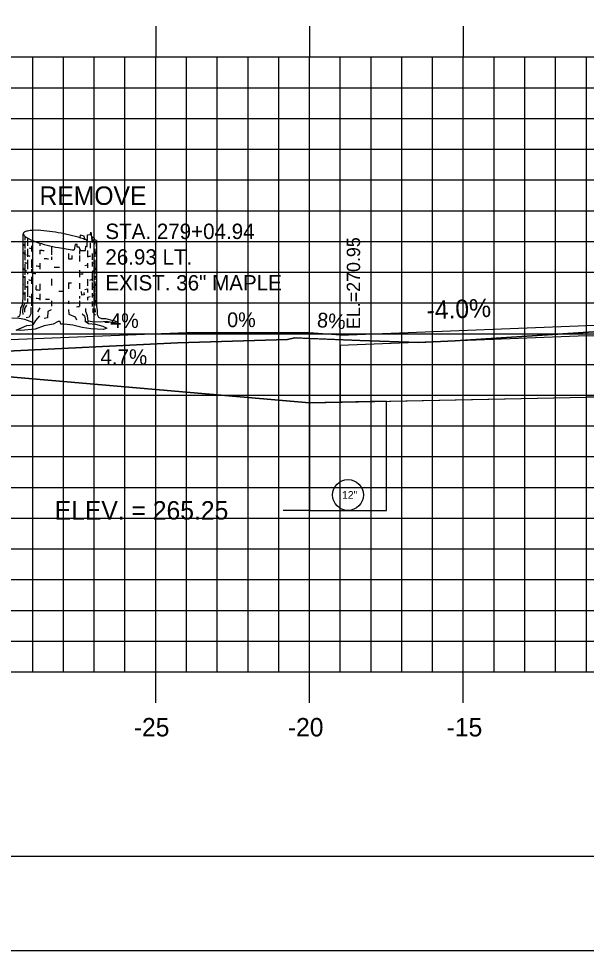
# Model space of a CAD drawing. Extents: x 854899 to 855069, y 366268 to 366378.
# Drawn here: x 854952.32 to 854970.77, y 366268.18 to 366298.48 of the extents above; entities that cross this region are included whole.
import ezdxf

# ---------------------------------------------------------------- set-up
doc = ezdxf.new("R2010")
doc.units = 0
for name, color, linetype in [('ANNOTATION', 7, 'Continuous'), ('BORDER', 7, 'Continuous'), ('D_Roadway_Drive_Gravel_LT', 7, 'Continuous'), ('D_Roadway_Drive_Gravel_RT', 7, 'Continuous'), ('D_Roadway_Drive_SubGrade', 7, 'Continuous'), ('D_Roadway_Edge_Shoulder', 7, 'Continuous'), ('D_Roadway_SubGrade', 7, 'Continuous'), ('D_Text_Monospaced', 7, 'Continuous'), ('D_Text_Standard', 7, 'Continuous'), ('H_V ANNOTATION', 7, 'Continuous'), ('JUNK COM EXC', 7, 'Continuous'), ('junk strct exc', 7, 'Continuous'), ('MAJOR', 7, 'Continuous'), ('MINOR', 7, 'Continuous'), ('PDRAIN', 7, 'Continuous'), ('PLOT BOUNDARY', 7, 'Continuous'), ('S_Roadway_Centerline', 7, 'Continuous'), ('S_Trees_Decid_Pay', 7, 'Continuous'), ('TEXT', 7, 'Continuous')]:
    doc.layers.add(name, color=color, linetype=linetype)

msp = doc.modelspace()

# ---------------------------------------------------------------- linework, layer by layer
at = {"layer": 'BORDER'}
msp.add_line((854906.774, 366271.236), (855066.774, 366271.236), dxfattribs=at)
at = {"layer": 'D_Roadway_Drive_Gravel_LT'}
for p, q in [((854961.774, 366288.264), (854957.774, 366288.264)), ((854962.774, 366288.184), (854961.774, 366288.264))]:
    msp.add_line(p, q, dxfattribs=at)
at = {"layer": 'D_Roadway_Drive_Gravel_RT'}
msp.add_line((854957.774, 366288.264), (854951.774, 366288.024), dxfattribs=at)
at = {"layer": 'D_Roadway_Drive_SubGrade'}
for p, q in [((854961.774, 366285.991), (854951.774, 366286.853)), ((854962.774, 366286.011), (854961.774, 366285.991))]:
    msp.add_line(p, q, dxfattribs=at)
at = {"layer": 'D_Roadway_Edge_Shoulder'}
msp.add_lwpolyline([(854962.774, 366288.184), (854970.774, 366288.504), (854981.774, 366288.674), (854992.774, 366288.453), (855000.774, 366288.133)], dxfattribs=at)
at = {"layer": 'D_Roadway_SubGrade'}
for points in [[(854970.774, 366288.171), (854962.774, 366287.851), (854962.774, 366286.011), (854970.774, 366286.171)], [(854970.774, 366286.171), (854970.774, 366288.171), (854981.774, 366288.34), (854992.774, 366288.12), (854992.774, 366286.12), (854981.774, 366286.34)]]:
    msp.add_lwpolyline(points, close=True, dxfattribs=at)
at = {"layer": 'D_Text_Standard'}
msp.add_lwpolyline([(854961.774, 366282.49), (854961.597, 366282.49), (854960.917, 366282.49)], dxfattribs=at)
at = {"layer": 'JUNK COM EXC'}
msp.add_lwpolyline([(855001.774, 366288.529), (854999.893, 366288.419), (854999.77, 366288.409), (854996.433, 366288.257), (854996.105, 366288.282), (854993.573, 366288.403), (854989.068, 366288.497), (854982.457, 366288.64), (854977.246, 366288.416), (854971.338, 366288.32), (854966.506, 366288), (854965.316, 366287.948), (854963.414, 366288.013), (854961.774, 366288.084), (854961.774, 366285.991), (854970.774, 366286.171), (854981.774, 366286.34), (854992.774, 366286.12), (855001.778, 366285.94), (855001.778, 366287.562)], dxfattribs=at)
msp.add_lwpolyline([(854961.774, 366285.991), (854961.774, 366288.084), (854961.286, 366288.106), (854961.059, 366288.051), (854957.486, 366287.942), (854945.963, 366287.37), (854939.471, 366287.163), (854939.471, 366285.996), (854951.774, 366286.853)], close=True, dxfattribs=at)
at = {"layer": 'junk strct exc'}
msp.add_lwpolyline([(854961.774, 366285.991), (854961.774, 366282.49), (854964.274, 366282.49), (854964.274, 366286.041)], close=True, dxfattribs=at)
at = {"layer": 'MAJOR'}
for p, q in [((854956.774, 366298.238), (854956.774, 366297.236)), ((854961.774, 366298.238), (854961.774, 366297.236)), ((854966.774, 366298.238), (854966.774, 366297.236)), ((854911.774, 366297.236), (855051.774, 366297.236)), ((854911.774, 366297.236), (855051.774, 366297.236)), ((854956.774, 366277.236), (854956.774, 366297.236)), ((854961.774, 366277.236), (854961.774, 366297.236)), ((854966.774, 366277.236), (854966.774, 366297.236)), ((854911.774, 366292.236), (855051.774, 366292.236)), ((854911.774, 366287.236), (855051.774, 366287.236)), ((854911.774, 366282.236), (855051.774, 366282.236)), ((854911.774, 366277.236), (855051.774, 366277.236)), ((854911.774, 366277.236), (855051.774, 366277.236)), ((854956.774, 366276.234), (854956.774, 366277.236)), ((854961.774, 366276.234), (854961.774, 366277.236)), ((854966.774, 366276.234), (854966.774, 366277.236))]:
    msp.add_line(p, q, dxfattribs=at)
at = {"layer": 'MINOR'}
for p, q in [((854952.774, 366277.236), (854952.774, 366297.236)), ((854953.774, 366277.236), (854953.774, 366297.236)), ((854954.774, 366277.236), (854954.774, 366297.236)), ((854955.774, 366277.236), (854955.774, 366297.236)), ((854957.774, 366277.236), (854957.774, 366297.236)), ((854958.774, 366277.236), (854958.774, 366297.236)), ((854959.774, 366277.236), (854959.774, 366297.236)), ((854960.774, 366277.236), (854960.774, 366297.236)), ((854962.774, 366277.236), (854962.774, 366297.236)), ((854963.774, 366277.236), (854963.774, 366297.236)), ((854964.774, 366277.236), (854964.774, 366297.236)), ((854965.774, 366277.236), (854965.774, 366297.236)), ((854967.774, 366277.236), (854967.774, 366297.236)), ((854968.774, 366277.236), (854968.774, 366297.236)), ((854969.774, 366277.236), (854969.774, 366297.236)), ((854970.774, 366277.236), (854970.774, 366297.236)), ((854911.774, 366296.236), (855051.774, 366296.236)), ((854911.774, 366295.236), (855051.774, 366295.236)), ((854911.774, 366294.236), (855051.774, 366294.236)), ((854911.774, 366293.236), (855051.774, 366293.236)), ((854911.774, 366291.236), (855051.774, 366291.236)), ((854911.774, 366290.236), (855051.774, 366290.236)), ((854911.774, 366289.236), (855051.774, 366289.236)), ((854911.774, 366288.236), (855051.774, 366288.236)), ((854911.774, 366286.236), (855051.774, 366286.236)), ((854911.774, 366285.236), (855051.774, 366285.236)), ((854911.774, 366284.236), (855051.774, 366284.236)), ((854911.774, 366283.236), (855051.774, 366283.236)), ((854911.774, 366281.236), (855051.774, 366281.236)), ((854911.774, 366280.236), (855051.774, 366280.236)), ((854911.774, 366279.236), (855051.774, 366279.236)), ((854911.774, 366278.236), (855051.774, 366278.236))]:
    msp.add_line(p, q, dxfattribs=at)
at = {"layer": 'PDRAIN'}
msp.add_lwpolyline([(854961.774, 366285.991), (854961.774, 366282.49), (854964.274, 366282.49), (854964.274, 366285.991)], dxfattribs=at)
msp.add_circle((854963.024, 366282.99), 0.5, dxfattribs=at)
at = {"layer": 'PLOT BOUNDARY'}
msp.add_lwpolyline([(854898.681, 366268.177), (855068.681, 366268.177), (855068.681, 366378.177), (854898.681, 366378.177)], close=True, dxfattribs=at)
at = {"layer": 'S_Roadway_Centerline'}
msp.add_lwpolyline([(854920.631, 366286.642), (854924.888, 366286.755), (854939.58, 366287.166), (854945.963, 366287.37), (854957.486, 366287.942), (854961.059, 366288.051), (854961.286, 366288.106), (854963.414, 366288.013), (854965.316, 366287.948), (854966.506, 366288), (854971.338, 366288.32), (854977.246, 366288.416), (854982.457, 366288.64), (854989.068, 366288.497), (854993.573, 366288.403), (854996.105, 366288.282), (854996.433, 366288.257), (854999.77, 366288.409), (854999.893, 366288.419), (855006.72, 366288.819), (855009.438, 366288.75)], dxfattribs=at)
at = {"layer": 'S_Trees_Decid_Pay'}
for p, q in [((854952.519, 366291.395), (854952.519, 366291.274)), ((854952.519, 366291.223), (854952.519, 366291.009)), ((854952.6, 366291.35), (854952.6, 366291.097)), ((854953.004, 366291.184), (854953.004, 366291.097)), ((854954.644, 366291.192), (854954.644, 366291.017)), ((854952.519, 366290.963), (854952.519, 366290.625)), ((854952.6, 366291.001), (854952.6, 366290.737)), ((854952.732, 366291.097), (854952.732, 366290.906)), ((854953.004, 366290.956), (854953.004, 366290.817)), ((854953.388, 366291.083), (854953.388, 366290.803)), ((854954.298, 366290.945), (854954.298, 366290.826)), ((854954.559, 366290.943), (854954.559, 366290.738)), ((854954.794, 366290.992), (854954.794, 366290.737)), ((854952.6, 366290.64), (854952.6, 366290.331)), ((854952.732, 366290.654), (854952.732, 366290.377)), ((854953.388, 366290.737), (854953.388, 366290.634)), ((854953.934, 366290.846), (854953.934, 366290.666)), ((854954.06, 366290.673), (854954.055, 366290.78)), ((854954.298, 366290.774), (854954.298, 366290.589)), ((854954.708, 366290.846), (854954.708, 366290.634)), ((854954.708, 366290.568), (854954.708, 366290.42)), ((854954.794, 366290.64), (854954.794, 366290.171)), ((854952.519, 366290.509), (854952.519, 366290.148)), ((854952.732, 366290.331), (854952.732, 366290.223)), ((854953.004, 366290.531), (854953.004, 366290.339)), ((854954.298, 366290.303), (854954.298, 366290.074)), ((854954.559, 366290.531), (854954.559, 366290.377)), ((854952.519, 366290.111), (854952.519, 366289.662)), ((854952.6, 366290.243), (854952.6, 366290.177)), ((854952.732, 366290.088), (854952.732, 366289.86)), ((854953.388, 366290.022), (854953.388, 366289.802)), ((854954.559, 366290.014), (854954.559, 366289.794)), ((854954.708, 366290.243), (854954.708, 366289.942)), ((854954.794, 366290.119), (854954.794, 366289.986)), ((854952.6, 366289.942), (854952.6, 366289.845)), ((854952.6, 366289.794), (854952.6, 366289.434)), ((854953.004, 366289.86), (854953.004, 366289.652)), ((854953.934, 366289.888), (854953.934, 366289.691)), ((854954.298, 366289.876), (854954.298, 366289.691)), ((854954.559, 366289.694), (854954.559, 366289.574)), ((854954.708, 366289.905), (854954.708, 366289.662)), ((854954.794, 366289.928), (854954.794, 366289.602)), ((854952.519, 366289.597), (854952.519, 366289.314)), ((854952.6, 366289.382), (854952.6, 366289.215)), ((854952.732, 366289.53), (854952.732, 366289.147)), ((854953.004, 366289.53), (854953.004, 366289.331)), ((854954.298, 366289.456), (854954.298, 366289.379)), ((854954.559, 366289.423), (854954.559, 366289.324)), ((854954.708, 366289.551), (854954.708, 366289.411)), ((854954.794, 366289.574), (854954.794, 366289.154)), ((854953.009, 366289.074), (854952.929, 366288.942)), ((854953.388, 366289.302), (854953.388, 366289.129)), ((854953.934, 366289.308), (854953.934, 366289.205)), ((854954.298, 366289.302), (854954.298, 366289.129)), ((854954.708, 366289.279), (854954.708, 366289.123)), ((854954.79, 366289.051), (854954.805, 366288.933))]:
    msp.add_line(p, q, dxfattribs=at)
for points in [[(854952.295, 366288.781), (854952.357, 366288.818), (854952.381, 366288.904), (854952.393, 366289.074), (854952.439, 366289.16), (854952.467, 366289.4), (854952.467, 366291.486)], [(854954.488, 366290.938), (854954.496, 366291.083), (854954.541, 366291.075), (854954.556, 366291.45), (854954.65, 366291.457), (854954.664, 366291.537), (854954.702, 366291.2), (854954.747, 366291.295), (854954.767, 366291.14), (854954.844, 366291.266), (854954.838, 366291.076)], [(854954.844, 366291.266), (854954.844, 366289.129), (854954.865, 366288.987), (854954.871, 366288.861), (854954.914, 366288.774), (854955.006, 366288.725), (854955.142, 366288.725), (854955.386, 366288.669), (854955.552, 366288.62), (854955.41, 366288.589), (854955.173, 366288.627), (854954.963, 366288.614), (854954.702, 366288.62), (854954.578, 366288.639), (854954.548, 366288.596), (854954.485, 366288.639), (854954.584, 366288.571), (854954.819, 366288.546), (854955.05, 366288.484), (854955.18, 366288.414), (854955.08, 366288.371), (854954.659, 366288.39), (854954.38, 366288.433), (854954.082, 366288.509), (854953.796, 366288.546), (854953.691, 366288.546), (854953.672, 366288.627), (854953.604, 366288.633), (854953.437, 366288.546), (854953.151, 366288.49), (854952.853, 366288.383), (854952.393, 366288.334), (854952.239, 366288.347), (854952.581, 366288.497), (854952.785, 366288.528), (854952.773, 366288.602), (854952.513, 366288.701), (854952.338, 366288.732), (854952.097, 366288.744)], [(854954.466, 366291.305), (854954.445, 366291.412), (854954.313, 366291.443), (854954.306, 366291.355)], [(854954.844, 366291.266), (854954.798, 366291.289), (854954.776, 366291.354), (854954.724, 366291.377), (854954.691, 366291.303)], [(854954.327, 366290.943), (854954.29, 366291.046), (854954.224, 366291.052), (854954.224, 366291.134), (854954.15, 366291.14), (854954.125, 366290.96)], [(854952.891, 366289.665), (854952.892, 366289.742), (854952.9, 366289.808)], [(854954.436, 366289.574), (854954.445, 366289.499), (854954.371, 366289.494), (854954.356, 366289.61)], [(854952.517, 366289.242), (854952.457, 366289.081), (854952.443, 366288.956), (854952.451, 366288.859)], [(854952.575, 366289.161), (854952.503, 366289.058), (854952.503, 366288.933)], [(854952.715, 366289.087), (854952.715, 366288.882), (854952.657, 366288.772), (854952.56, 366288.756)], [(854954.578, 366288.639), (854954.559, 366288.818), (854954.498, 366288.954), (854954.504, 366289.055)], [(854954.724, 366289.058), (854954.731, 366288.933), (854954.813, 366288.839)], [(854952.785, 366288.528), (854952.871, 366288.669), (854953.003, 366288.812)], [(854953.37, 366289.013), (854953.267, 366288.962), (854953.252, 366288.756), (854953.149, 366288.727)], [(854953.935, 366289.022), (854953.953, 366288.868), (854954.15, 366288.787), (854954.195, 366288.684)], [(854954.387, 366288.886), (854954.461, 366288.818), (854954.479, 366288.719), (854954.485, 366288.639)]]:
    msp.add_lwpolyline(points, dxfattribs=at)
for centre, radius, start, end in [((854952.514, 366291.486), 0.0467, 169.2221, 180.9043), ((854952.521, 366291.487), 0.0544, 180.9043, 191.7221), ((854952.514, 366291.486), 0.0467, 157.54, 169.2221), ((854952.531, 366291.489), 0.0645, 191.7221, 204.3989), ((854952.521, 366291.484), 0.0544, 146.7221, 157.54), ((854952.529, 366291.478), 0.0645, 134.0453, 146.7221), ((854952.559, 366291.447), 0.107, 124.2221, 134.0453), ((854952.591, 366291.4), 0.164, 110.0157, 124.2221), ((854952.699, 366291.104), 0.48, 101.7221, 110.0157), ((854952.865, 366290.301), 1.299, 86.3056, 101.7221), ((854952.554, 366285.485), 6.126, 79.2221, 86.3056), ((854952.554, 366285.485), 6.126, 72.1387, 79.2221), ((854952.57, 366291.506), 0.107, 204.3989, 214.2221), ((854952.617, 366291.538), 0.164, 214.2221, 228.4286), ((854952.826, 366291.774), 0.48, 228.4286, 236.7221), ((854953.276, 366292.46), 1.299, 236.7221, 252.1387), ((854954.756, 366297.053), 6.126, 252.1387, 259.2221), ((854954.035, 366290.078), 1.299, 66.6931, 72.1387), ((854952.521, 366291.16), 0.0554, 191.6815, 202.5), ((854952.522, 366290.899), 0.0554, 191.6815, 202.5), ((854952.531, 366291.164), 0.0657, 202.5, 215.1737), ((854952.532, 366290.903), 0.0657, 202.5, 215.1737), ((854952.566, 366291.189), 0.109, 215.1737, 225), ((854952.567, 366290.928), 0.109, 215.1737, 225), ((854952.607, 366291.229), 0.166, 225, 238.33), ((854953.079, 366292.249), 1.292, 250.9084, 254.4349), ((854953.654, 366296.837), 5.916, 263.6913, 265.0485), ((854954.756, 366297.053), 6.126, 259.2221, 264.0853), ((854954.756, 366297.053), 6.126, 265.9754, 266.3056), ((854954.446, 366292.237), 1.299, 266.3056, 271.8711), ((854954.744, 366290.928), 0.109, 315, 324.8263), ((854954.779, 366290.903), 0.0657, 324.8263, 337.5), ((854954.789, 366290.899), 0.0554, 337.5, 348.3185), ((854954.796, 366290.897), 0.0476, 348.3185, 0), ((854952.608, 366290.969), 0.166, 225, 239.1924), ((854952.608, 366290.705), 0.166, 238.3999, 239.1924), ((854952.77, 366291.241), 0.484, 239.1924, 242.5838), ((854952.77, 366290.978), 0.484, 239.1924, 247.5), ((854953.079, 366291.988), 1.292, 247.5, 251.9171), ((854953.655, 366296.576), 5.916, 265.1076, 266.4618), ((854953.655, 366296.576), 5.916, 272.6957, 273.9224), ((854954.231, 366291.988), 1.292, 284.7144, 289.3881), ((854954.54, 366290.978), 0.484, 292.5, 300.8076), ((854954.703, 366290.969), 0.166, 300.8076, 315), ((854954.703, 366290.705), 0.166, 300.8076, 302.9622), ((854952.522, 366290.378), 0.0554, 191.6815, 202.5), ((854952.532, 366290.382), 0.0657, 202.5, 215.1737), ((854952.567, 366290.407), 0.109, 215.1737, 225), ((854952.608, 366290.448), 0.166, 225, 239.1924), ((854952.77, 366290.721), 0.484, 239.1924, 245.3628), ((854953.079, 366291.724), 1.292, 247.5, 248.1929), ((854953.079, 366291.724), 1.292, 261.6338, 262.8454), ((854953.655, 366296.312), 5.916, 262.8454, 263.6816), ((854953.655, 366296.312), 5.916, 268.2292, 269.8838), ((854954.231, 366291.724), 1.292, 280.7368, 284.7144), ((854954.231, 366291.467), 1.292, 291.5158, 292.5), ((854954.231, 366291.724), 1.292, 291.6463, 292.5), ((854954.54, 366290.721), 0.484, 294.2275, 300.8076), ((854954.703, 366290.448), 0.166, 300.8076, 315), ((854954.744, 366290.407), 0.109, 315, 324.8263), ((854954.779, 366290.382), 0.0657, 324.8263, 337.5), ((854954.789, 366290.378), 0.0554, 337.5, 348.3185), ((854954.796, 366290.377), 0.0476, 348.3185, 0), ((854952.522, 366290.121), 0.0554, 191.6815, 202.5), ((854952.532, 366290.125), 0.0657, 202.5, 215.1737), ((854952.567, 366290.15), 0.109, 215.1737, 225), ((854952.608, 366290.19), 0.166, 225, 237.9306), ((854953.079, 366291.209), 1.292, 249.8999, 254.3895), ((854953.079, 366291.467), 1.292, 254.3895, 260.7435), ((854953.655, 366296.055), 5.916, 276.2405, 277.1546), ((854954.231, 366291.467), 1.292, 277.1546, 278.1274), ((854954.231, 366291.209), 1.292, 288.201, 292.5), ((854954.703, 366290.19), 0.166, 300.8076, 315), ((854954.744, 366290.15), 0.109, 315, 324.8263), ((854954.779, 366290.125), 0.0657, 324.8263, 337.5), ((854954.789, 366290.121), 0.0554, 337.5, 348.3185), ((854954.796, 366290.119), 0.0476, 348.3185, 0), ((854952.522, 366289.855), 0.0554, 191.6815, 202.5), ((854952.608, 366289.925), 0.166, 237.9306, 239.1924), ((854952.77, 366290.198), 0.484, 239.1924, 247.5), ((854953.079, 366290.944), 1.292, 261.6205, 262.8454), ((854953.655, 366295.532), 5.916, 262.8454, 263.6816), ((854953.655, 366295.797), 5.916, 272.6957, 273.7279), ((854954.231, 366290.944), 1.292, 280.7537, 284.7144), ((854954.231, 366290.944), 1.292, 291.6463, 292.5), ((854954.54, 366290.198), 0.484, 292.5, 300.8076), ((854954.703, 366289.925), 0.166, 300.8076, 315), ((854954.744, 366289.884), 0.109, 315, 324.8263), ((854954.779, 366289.859), 0.0657, 324.8263, 337.5), ((854954.789, 366289.855), 0.0554, 337.5, 348.3185), ((854954.796, 366289.854), 0.0476, 348.3185, 0), ((854952.522, 366289.583), 0.0554, 191.6815, 202.5), ((854952.532, 366289.587), 0.0657, 202.5, 215.1737), ((854952.567, 366289.612), 0.109, 215.1737, 225), ((854952.608, 366289.653), 0.166, 225, 237.9306), ((854953.079, 366290.672), 1.292, 250.8466, 254.3895), ((854953.079, 366290.672), 1.292, 261.6338, 262.8454), ((854953.655, 366295.26), 5.916, 262.8454, 263.6816), ((854953.655, 366295.26), 5.916, 265.539, 266.7363), ((854953.655, 366295.532), 5.916, 269.7243, 270), ((854953.655, 366295.532), 5.916, 270, 271.0793), ((854954.231, 366290.672), 1.292, 284.7144, 288.6336), ((854954.54, 366289.926), 0.484, 292.5, 297.266), ((854952.77, 366289.668), 0.484, 243.4501, 247.5), ((854953.07, 366290.418), 1.292, 247.9396, 248.6304), ((854953.655, 366295.003), 5.916, 275.2344, 276.2169), ((854954.231, 366290.415), 1.292, 291.6463, 292.5), ((854954.54, 366289.668), 0.484, 292.5, 300.8076), ((854954.703, 366289.396), 0.166, 300.8076, 315), ((854954.744, 366289.355), 0.109, 315, 324.8263), ((854954.779, 366289.33), 0.0657, 324.8263, 337.5), ((854954.789, 366289.326), 0.0554, 337.5, 348.3185), ((854954.796, 366289.324), 0.0476, 348.3185, 0)]:
    msp.add_arc(centre, radius, start, end, dxfattribs=at)

# ---------------------------------------------------------------- texts
at = {"layer": 'ANNOTATION'}
msp.add_text('REMOVE', height=0.6, dxfattribs=at).set_placement((854952.995, 366292.425))
msp.add_text('-4.0%', height=0.6, rotation=2.2906, dxfattribs=at).set_placement((854965.59, 366288.698))
at = {"layer": 'D_Roadway_Drive_Gravel_LT'}
for s, p in [(' -4%', (854954.902, 366288.422)), ('0%', (854959.096, 366288.449))]:
    msp.add_text(s, height=0.48, dxfattribs=at).set_placement(p)
msp.add_text('8%', height=0.48, rotation=355.4261, dxfattribs=at).set_placement((854962.005, 366288.451))
at = {"layer": 'D_Text_Monospaced'}
for s, height, p in [('STA. 279+04.94', 0.49998, (854955.137, 366291.315)), ('26.93 LT.', 0.5, (854955.137, 366290.481)), ('EXIST. 36" MAPLE', 0.49998, (854955.137, 366289.641))]:
    msp.add_text(s, height=height, dxfattribs=at).set_placement(p)
at = {"layer": 'D_Text_Standard'}
msp.add_text(' EL.=270.95', height=0.4335, rotation=90, dxfattribs=at).set_placement((854963.418, 366288.228))
msp.add_text('ELEV. = 265.25', height=0.6, dxfattribs=at).set_placement((854953.49, 366282.19))
at = {"layer": 'H_V ANNOTATION'}
for s, p in [('-25', (854956.06, 366275.136)), ('-20', (854961.068, 366275.136)), ('-15', (854966.231, 366275.136))]:
    msp.add_text(s, height=0.6, dxfattribs=at).set_placement(p)
at = {"layer": 'PDRAIN'}
msp.add_text('12"', height=0.25, dxfattribs=at).set_placement((854962.833, 366282.865))
at = {"layer": 'TEXT'}
msp.add_text('4.7%', height=0.5, dxfattribs=at).set_placement((854954.974, 366287.229))

doc.saveas('drawing.dxf')
